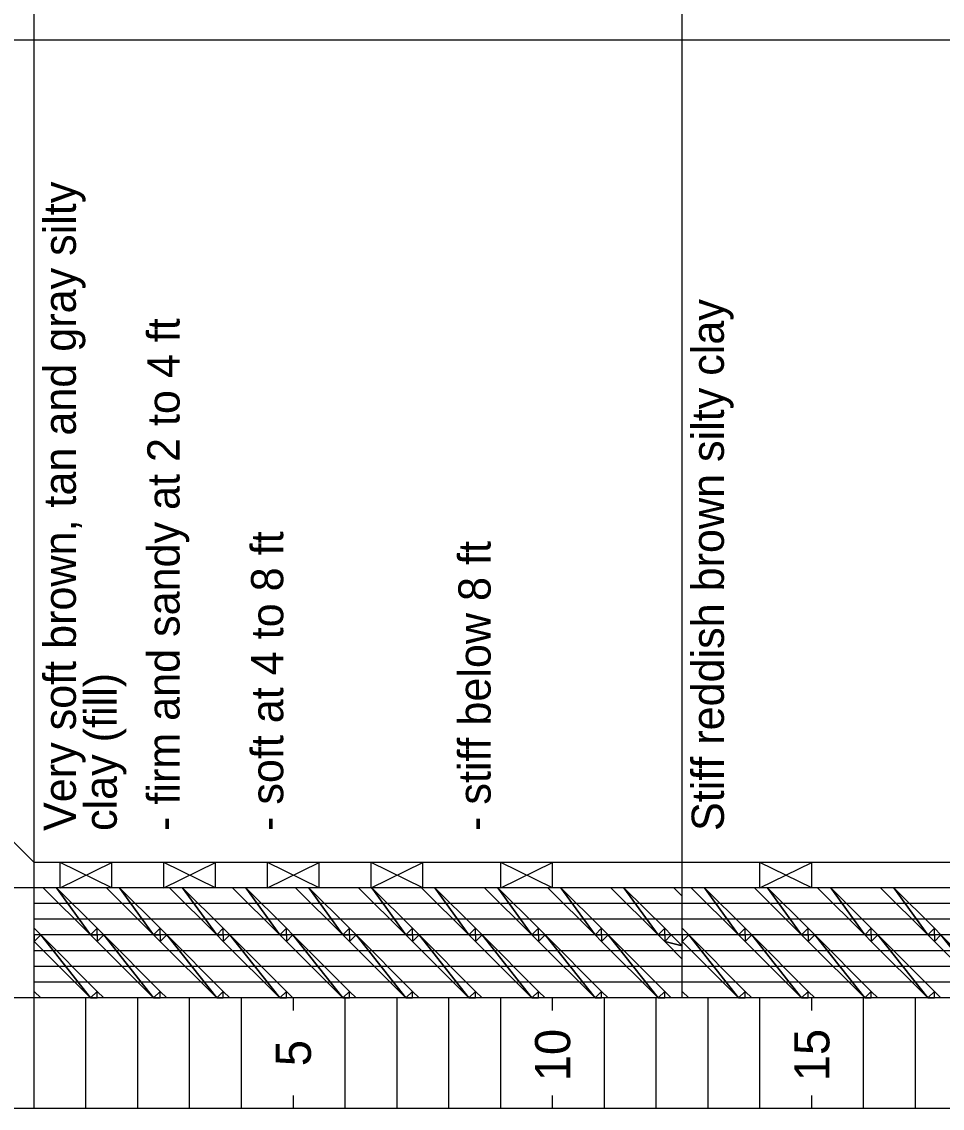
# Model space of a CAD drawing. Extents: x 1313964 to 1316843, y 2087046 to 2096619.
# Drawn here: x 1314089.05 to 1314106.81, y 2089818.7 to 2089839.67 of the extents above; entities that cross this region are included whole.
import ezdxf

# ---------------------------------------------------------------- set-up
doc = ezdxf.new("R2010")
doc.units = 0
doc.layers.add('B-Sub-Contour', color=7, linetype='Continuous')

msp = doc.modelspace()

# ---------------------------------------------------------------- linework, layer by layer
at = {"layer": 'B-Sub-Contour'}
for points in [[(1314136.725, 2089818.705), (1314136.725, 2089861.576), (1314075.306, 2089861.576), (1314075.306, 2089818.705), (1314136.725, 2089818.705)], [(1314089.292, 2089818.705), (1314089.292, 2089861.576)], [(1314101.792, 2089839.319), (1314101.792, 2089859.752)], [(1314134.292, 2089839.319), (1314082.603, 2089839.319)], [(1314101.792, 2089823.448), (1314101.792, 2089839.319)], [(1314089.292, 2089823.448), (1314088.745, 2089823.995)], [(1314134.292, 2089823.448), (1314089.292, 2089823.448)], [(1314089.792, 2089822.961), (1314090.792, 2089823.448)], [(1314090.792, 2089822.961), (1314089.792, 2089823.448)], [(1314089.792, 2089822.961), (1314089.792, 2089823.448)], [(1314090.792, 2089822.961), (1314090.792, 2089823.448)], [(1314091.792, 2089822.961), (1314092.792, 2089823.448)], [(1314092.792, 2089822.961), (1314091.792, 2089823.448)], [(1314091.792, 2089822.961), (1314091.792, 2089823.448)], [(1314092.792, 2089822.961), (1314092.792, 2089823.448)], [(1314093.792, 2089822.961), (1314094.792, 2089823.448)], [(1314094.792, 2089822.961), (1314093.792, 2089823.448)], [(1314093.792, 2089822.961), (1314093.792, 2089823.448)], [(1314094.792, 2089822.961), (1314094.792, 2089823.448)], [(1314095.792, 2089822.961), (1314096.792, 2089823.448)], [(1314096.792, 2089822.961), (1314095.792, 2089823.448)], [(1314095.792, 2089822.961), (1314095.792, 2089823.448)], [(1314096.792, 2089822.961), (1314096.792, 2089823.448)], [(1314098.292, 2089822.961), (1314099.292, 2089823.448)], [(1314099.292, 2089822.961), (1314098.292, 2089823.448)], [(1314098.292, 2089822.961), (1314098.292, 2089823.448)], [(1314099.292, 2089822.961), (1314099.292, 2089823.448)], [(1314101.792, 2089822.961), (1314101.792, 2089823.448)], [(1314103.292, 2089822.961), (1314104.292, 2089823.448)], [(1314104.292, 2089822.961), (1314103.292, 2089823.448)], [(1314103.292, 2089822.961), (1314103.292, 2089823.448)], [(1314104.292, 2089822.961), (1314104.292, 2089823.448)], [(1314134.292, 2089822.961), (1314082.603, 2089822.961)], [(1314101.792, 2089820.833), (1314101.792, 2089822.961)], [(1314101.792, 2089822.657), (1314089.292, 2089822.657)], [(1314117.292, 2089822.657), (1314101.792, 2089822.657)], [(1314101.792, 2089822.353), (1314089.292, 2089822.353)], [(1314117.292, 2089822.353), (1314101.792, 2089822.353)], [(1314101.792, 2089822.049), (1314089.292, 2089822.049)], [(1314117.292, 2089822.049), (1314101.792, 2089822.049)], [(1314101.792, 2089821.745), (1314089.292, 2089821.745)], [(1314117.292, 2089821.745), (1314101.792, 2089821.745)], [(1314101.792, 2089821.441), (1314089.292, 2089821.441)], [(1314117.292, 2089821.441), (1314101.792, 2089821.441)], [(1314101.792, 2089821.137), (1314089.292, 2089821.137)], [(1314117.292, 2089821.137), (1314101.792, 2089821.137)], [(1314134.292, 2089820.833), (1314082.603, 2089820.833)], [(1314089.292, 2089820.59), (1314089.292, 2089820.833)], [(1314089.292, 2089820.59), (1314089.292, 2089820.833)], [(1314090.292, 2089818.705), (1314090.292, 2089820.833)], [(1314091.292, 2089818.705), (1314091.292, 2089820.833)], [(1314091.292, 2089818.705), (1314091.292, 2089820.833)], [(1314092.292, 2089818.705), (1314092.292, 2089820.833)], [(1314093.292, 2089818.705), (1314093.292, 2089820.833)], [(1314093.292, 2089818.705), (1314093.292, 2089820.833)], [(1314094.292, 2089820.59), (1314094.292, 2089820.833)], [(1314095.292, 2089818.705), (1314095.292, 2089820.833)], [(1314095.292, 2089818.705), (1314095.292, 2089820.833)], [(1314096.292, 2089818.705), (1314096.292, 2089820.833)], [(1314097.292, 2089818.705), (1314097.292, 2089820.833)], [(1314097.292, 2089818.705), (1314097.292, 2089820.833)], [(1314098.292, 2089818.705), (1314098.292, 2089820.833)], [(1314099.292, 2089820.59), (1314099.292, 2089820.833)], [(1314099.292, 2089820.59), (1314099.292, 2089820.833)], [(1314100.292, 2089818.705), (1314100.292, 2089820.833)], [(1314101.292, 2089818.705), (1314101.292, 2089820.833)], [(1314101.292, 2089818.705), (1314101.292, 2089820.833)], [(1314102.292, 2089818.705), (1314102.292, 2089820.833)], [(1314103.292, 2089818.705), (1314103.292, 2089820.833)], [(1314103.292, 2089818.705), (1314103.292, 2089820.833)], [(1314104.292, 2089820.59), (1314104.292, 2089820.833)], [(1314105.292, 2089818.705), (1314105.292, 2089820.833)], [(1314105.292, 2089818.705), (1314105.292, 2089820.833)], [(1314106.292, 2089818.705), (1314106.292, 2089820.833)], [(1314089.292, 2089818.705), (1314089.292, 2089818.948)], [(1314089.292, 2089818.705), (1314089.292, 2089818.948)], [(1314094.292, 2089818.705), (1314094.292, 2089818.948)], [(1314099.292, 2089818.705), (1314099.292, 2089818.948)], [(1314099.292, 2089818.705), (1314099.292, 2089818.948)], [(1314104.292, 2089818.705), (1314104.292, 2089818.948)]]:
    msp.add_lwpolyline(points, dxfattribs=at)
for points in [[(1314090.381, 2089822.049), (1314089.724, 2089822.961), (1314089.468, 2089822.961), (1314090.381, 2089822.049)], [(1314090.381, 2089822.049), (1314090.509, 2089822.177), (1314089.724, 2089822.961), (1314090.381, 2089822.049)], [(1314091.597, 2089822.049), (1314090.94, 2089822.961), (1314090.685, 2089822.961), (1314091.597, 2089822.049)], [(1314091.597, 2089822.049), (1314091.725, 2089822.177), (1314090.94, 2089822.961), (1314091.597, 2089822.049)], [(1314092.813, 2089822.049), (1314092.157, 2089822.961), (1314091.901, 2089822.961), (1314092.813, 2089822.049)], [(1314092.813, 2089822.049), (1314092.941, 2089822.177), (1314092.157, 2089822.961), (1314092.813, 2089822.049)], [(1314094.03, 2089822.049), (1314093.373, 2089822.961), (1314093.117, 2089822.961), (1314094.03, 2089822.049)], [(1314094.03, 2089822.049), (1314094.157, 2089822.177), (1314093.373, 2089822.961), (1314094.03, 2089822.049)], [(1314095.246, 2089822.049), (1314094.589, 2089822.961), (1314094.334, 2089822.961), (1314095.246, 2089822.049)], [(1314095.246, 2089822.049), (1314095.374, 2089822.177), (1314094.589, 2089822.961), (1314095.246, 2089822.049)], [(1314096.462, 2089822.049), (1314095.805, 2089822.961), (1314095.55, 2089822.961), (1314096.462, 2089822.049)], [(1314096.462, 2089822.049), (1314096.59, 2089822.177), (1314095.805, 2089822.961), (1314096.462, 2089822.049)], [(1314097.678, 2089822.049), (1314097.021, 2089822.961), (1314096.766, 2089822.961), (1314097.678, 2089822.049)], [(1314097.678, 2089822.049), (1314097.806, 2089822.177), (1314097.021, 2089822.961), (1314097.678, 2089822.049)], [(1314098.894, 2089822.049), (1314098.238, 2089822.961), (1314097.982, 2089822.961), (1314098.894, 2089822.049)], [(1314098.894, 2089822.049), (1314099.022, 2089822.177), (1314098.238, 2089822.961), (1314098.894, 2089822.049)], [(1314100.111, 2089822.049), (1314099.454, 2089822.961), (1314099.199, 2089822.961), (1314100.111, 2089822.049)], [(1314100.111, 2089822.049), (1314100.238, 2089822.177), (1314099.454, 2089822.961), (1314100.111, 2089822.049)], [(1314101.327, 2089822.049), (1314100.67, 2089822.961), (1314100.415, 2089822.961), (1314101.327, 2089822.049)], [(1314101.327, 2089822.049), (1314101.455, 2089822.177), (1314100.67, 2089822.961), (1314101.327, 2089822.049)], [(1314101.792, 2089822.8), (1314101.792, 2089822.961), (1314101.631, 2089822.961), (1314101.792, 2089822.8)], [(1314102.881, 2089822.049), (1314102.224, 2089822.961), (1314101.968, 2089822.961), (1314102.881, 2089822.049)], [(1314102.881, 2089822.049), (1314103.009, 2089822.177), (1314102.224, 2089822.961), (1314102.881, 2089822.049)], [(1314104.097, 2089822.049), (1314103.44, 2089822.961), (1314103.185, 2089822.961), (1314104.097, 2089822.049)], [(1314104.097, 2089822.049), (1314104.225, 2089822.177), (1314103.44, 2089822.961), (1314104.097, 2089822.049)], [(1314105.313, 2089822.049), (1314104.657, 2089822.961), (1314104.401, 2089822.961), (1314105.313, 2089822.049)], [(1314105.313, 2089822.049), (1314105.441, 2089822.177), (1314104.657, 2089822.961), (1314105.313, 2089822.049)], [(1314106.53, 2089822.049), (1314105.873, 2089822.961), (1314105.617, 2089822.961), (1314106.53, 2089822.049)], [(1314106.53, 2089822.049), (1314106.657, 2089822.177), (1314105.873, 2089822.961), (1314106.53, 2089822.049)], [(1314089.42, 2089822.049), (1314089.292, 2089822.049), (1314089.292, 2089822.177), (1314089.42, 2089822.049)], [(1314089.42, 2089822.049), (1314089.292, 2089822.049), (1314089.292, 2089821.922), (1314089.42, 2089822.049)], [(1314090.381, 2089820.833), (1314089.42, 2089822.049), (1314089.292, 2089821.922), (1314090.381, 2089820.833)], [(1314090.381, 2089820.833), (1314090.509, 2089820.961), (1314089.42, 2089822.049), (1314090.381, 2089820.833)], [(1314090.381, 2089822.049), (1314090.509, 2089822.049), (1314090.509, 2089822.177), (1314090.381, 2089822.049)], [(1314090.509, 2089822.049), (1314090.509, 2089821.922), (1314090.381, 2089822.049), (1314090.509, 2089822.049)], [(1314090.636, 2089822.049), (1314090.509, 2089822.049), (1314090.509, 2089822.177), (1314090.636, 2089822.049)], [(1314090.636, 2089822.049), (1314090.509, 2089822.049), (1314090.509, 2089821.922), (1314090.636, 2089822.049)], [(1314091.597, 2089820.833), (1314090.636, 2089822.049), (1314090.509, 2089821.922), (1314091.597, 2089820.833)], [(1314091.597, 2089820.833), (1314091.725, 2089820.961), (1314090.636, 2089822.049), (1314091.597, 2089820.833)], [(1314091.597, 2089822.049), (1314091.725, 2089822.049), (1314091.725, 2089822.177), (1314091.597, 2089822.049)], [(1314091.725, 2089822.049), (1314091.725, 2089821.922), (1314091.597, 2089822.049), (1314091.725, 2089822.049)], [(1314091.853, 2089822.049), (1314091.725, 2089822.049), (1314091.725, 2089822.177), (1314091.853, 2089822.049)], [(1314091.853, 2089822.049), (1314091.725, 2089822.049), (1314091.725, 2089821.922), (1314091.853, 2089822.049)], [(1314092.813, 2089820.833), (1314091.853, 2089822.049), (1314091.725, 2089821.922), (1314092.813, 2089820.833)], [(1314092.813, 2089820.833), (1314092.941, 2089820.961), (1314091.853, 2089822.049), (1314092.813, 2089820.833)], [(1314092.813, 2089822.049), (1314092.941, 2089822.049), (1314092.941, 2089822.177), (1314092.813, 2089822.049)], [(1314092.941, 2089822.049), (1314092.941, 2089821.922), (1314092.813, 2089822.049), (1314092.941, 2089822.049)], [(1314093.069, 2089822.049), (1314092.941, 2089822.049), (1314092.941, 2089822.177), (1314093.069, 2089822.049)], [(1314093.069, 2089822.049), (1314092.941, 2089822.049), (1314092.941, 2089821.922), (1314093.069, 2089822.049)], [(1314094.03, 2089820.833), (1314093.069, 2089822.049), (1314092.941, 2089821.922), (1314094.03, 2089820.833)], [(1314094.03, 2089820.833), (1314094.157, 2089820.961), (1314093.069, 2089822.049), (1314094.03, 2089820.833)], [(1314094.03, 2089822.049), (1314094.157, 2089822.049), (1314094.157, 2089822.177), (1314094.03, 2089822.049)], [(1314094.157, 2089822.049), (1314094.157, 2089821.922), (1314094.03, 2089822.049), (1314094.157, 2089822.049)], [(1314094.285, 2089822.049), (1314094.157, 2089822.049), (1314094.157, 2089822.177), (1314094.285, 2089822.049)], [(1314094.285, 2089822.049), (1314094.157, 2089822.049), (1314094.157, 2089821.922), (1314094.285, 2089822.049)], [(1314095.246, 2089820.833), (1314094.285, 2089822.049), (1314094.157, 2089821.922), (1314095.246, 2089820.833)], [(1314095.246, 2089820.833), (1314095.374, 2089820.961), (1314094.285, 2089822.049), (1314095.246, 2089820.833)], [(1314095.246, 2089822.049), (1314095.374, 2089822.049), (1314095.374, 2089822.177), (1314095.246, 2089822.049)], [(1314095.374, 2089822.049), (1314095.374, 2089821.922), (1314095.246, 2089822.049), (1314095.374, 2089822.049)], [(1314095.501, 2089822.049), (1314095.374, 2089822.049), (1314095.374, 2089822.177), (1314095.501, 2089822.049)], [(1314095.501, 2089822.049), (1314095.374, 2089822.049), (1314095.374, 2089821.922), (1314095.501, 2089822.049)], [(1314096.462, 2089820.833), (1314095.501, 2089822.049), (1314095.374, 2089821.922), (1314096.462, 2089820.833)], [(1314096.462, 2089820.833), (1314096.59, 2089820.961), (1314095.501, 2089822.049), (1314096.462, 2089820.833)], [(1314096.462, 2089822.049), (1314096.59, 2089822.049), (1314096.59, 2089822.177), (1314096.462, 2089822.049)], [(1314096.59, 2089822.049), (1314096.59, 2089821.922), (1314096.462, 2089822.049), (1314096.59, 2089822.049)], [(1314096.717, 2089822.049), (1314096.59, 2089822.049), (1314096.59, 2089822.177), (1314096.717, 2089822.049)], [(1314096.717, 2089822.049), (1314096.59, 2089822.049), (1314096.59, 2089821.922), (1314096.717, 2089822.049)], [(1314097.678, 2089820.833), (1314096.717, 2089822.049), (1314096.59, 2089821.922), (1314097.678, 2089820.833)], [(1314097.678, 2089820.833), (1314097.806, 2089820.961), (1314096.717, 2089822.049), (1314097.678, 2089820.833)], [(1314097.678, 2089822.049), (1314097.806, 2089822.049), (1314097.806, 2089822.177), (1314097.678, 2089822.049)], [(1314097.806, 2089822.049), (1314097.806, 2089821.922), (1314097.678, 2089822.049), (1314097.806, 2089822.049)], [(1314097.934, 2089822.049), (1314097.806, 2089822.049), (1314097.806, 2089822.177), (1314097.934, 2089822.049)], [(1314097.934, 2089822.049), (1314097.806, 2089822.049), (1314097.806, 2089821.922), (1314097.934, 2089822.049)], [(1314098.894, 2089820.833), (1314097.934, 2089822.049), (1314097.806, 2089821.922), (1314098.894, 2089820.833)], [(1314098.894, 2089820.833), (1314099.022, 2089820.961), (1314097.934, 2089822.049), (1314098.894, 2089820.833)], [(1314098.894, 2089822.049), (1314099.022, 2089822.049), (1314099.022, 2089822.177), (1314098.894, 2089822.049)], [(1314099.022, 2089822.049), (1314099.022, 2089821.922), (1314098.894, 2089822.049), (1314099.022, 2089822.049)], [(1314099.15, 2089822.049), (1314099.022, 2089822.049), (1314099.022, 2089822.177), (1314099.15, 2089822.049)], [(1314099.15, 2089822.049), (1314099.022, 2089822.049), (1314099.022, 2089821.922), (1314099.15, 2089822.049)], [(1314100.111, 2089820.833), (1314099.15, 2089822.049), (1314099.022, 2089821.922), (1314100.111, 2089820.833)], [(1314100.111, 2089820.833), (1314100.238, 2089820.961), (1314099.15, 2089822.049), (1314100.111, 2089820.833)], [(1314100.111, 2089822.049), (1314100.238, 2089822.049), (1314100.238, 2089822.177), (1314100.111, 2089822.049)], [(1314100.238, 2089822.049), (1314100.238, 2089821.922), (1314100.111, 2089822.049), (1314100.238, 2089822.049)], [(1314100.366, 2089822.049), (1314100.238, 2089822.049), (1314100.238, 2089822.177), (1314100.366, 2089822.049)], [(1314100.366, 2089822.049), (1314100.238, 2089822.049), (1314100.238, 2089821.922), (1314100.366, 2089822.049)], [(1314101.327, 2089820.833), (1314100.366, 2089822.049), (1314100.238, 2089821.922), (1314101.327, 2089820.833)], [(1314101.327, 2089820.833), (1314101.455, 2089820.961), (1314100.366, 2089822.049), (1314101.327, 2089820.833)], [(1314101.327, 2089822.049), (1314101.455, 2089822.049), (1314101.455, 2089822.177), (1314101.327, 2089822.049)], [(1314101.455, 2089822.049), (1314101.455, 2089821.922), (1314101.327, 2089822.049), (1314101.455, 2089822.049)], [(1314101.582, 2089822.049), (1314101.455, 2089822.049), (1314101.455, 2089822.177), (1314101.582, 2089822.049)], [(1314101.582, 2089822.049), (1314101.455, 2089822.049), (1314101.455, 2089821.922), (1314101.582, 2089822.049)], [(1314101.455, 2089821.922), (1314101.792, 2089821.839), (1314101.582, 2089822.049), (1314101.455, 2089821.922)], [(1314101.92, 2089822.049), (1314101.792, 2089822.049), (1314101.792, 2089822.177), (1314101.92, 2089822.049)], [(1314101.92, 2089822.049), (1314101.792, 2089822.049), (1314101.792, 2089821.922), (1314101.92, 2089822.049)], [(1314102.881, 2089820.833), (1314101.92, 2089822.049), (1314101.792, 2089821.922), (1314102.881, 2089820.833)], [(1314102.881, 2089820.833), (1314103.009, 2089820.961), (1314101.92, 2089822.049), (1314102.881, 2089820.833)], [(1314102.881, 2089822.049), (1314103.009, 2089822.049), (1314103.009, 2089822.177), (1314102.881, 2089822.049)], [(1314103.009, 2089822.049), (1314103.009, 2089821.922), (1314102.881, 2089822.049), (1314103.009, 2089822.049)], [(1314103.136, 2089822.049), (1314103.009, 2089822.049), (1314103.009, 2089822.177), (1314103.136, 2089822.049)], [(1314103.136, 2089822.049), (1314103.009, 2089822.049), (1314103.009, 2089821.922), (1314103.136, 2089822.049)], [(1314104.097, 2089820.833), (1314103.136, 2089822.049), (1314103.009, 2089821.922), (1314104.097, 2089820.833)], [(1314104.097, 2089820.833), (1314104.225, 2089820.961), (1314103.136, 2089822.049), (1314104.097, 2089820.833)], [(1314104.097, 2089822.049), (1314104.225, 2089822.049), (1314104.225, 2089822.177), (1314104.097, 2089822.049)], [(1314104.225, 2089822.049), (1314104.225, 2089821.922), (1314104.097, 2089822.049), (1314104.225, 2089822.049)], [(1314104.353, 2089822.049), (1314104.225, 2089822.049), (1314104.225, 2089822.177), (1314104.353, 2089822.049)], [(1314104.353, 2089822.049), (1314104.225, 2089822.049), (1314104.225, 2089821.922), (1314104.353, 2089822.049)], [(1314105.313, 2089820.833), (1314104.353, 2089822.049), (1314104.225, 2089821.922), (1314105.313, 2089820.833)], [(1314105.313, 2089820.833), (1314105.441, 2089820.961), (1314104.353, 2089822.049), (1314105.313, 2089820.833)], [(1314105.313, 2089822.049), (1314105.441, 2089822.049), (1314105.441, 2089822.177), (1314105.313, 2089822.049)], [(1314105.441, 2089822.049), (1314105.441, 2089821.922), (1314105.313, 2089822.049), (1314105.441, 2089822.049)], [(1314105.569, 2089822.049), (1314105.441, 2089822.049), (1314105.441, 2089822.177), (1314105.569, 2089822.049)], [(1314105.569, 2089822.049), (1314105.441, 2089822.049), (1314105.441, 2089821.922), (1314105.569, 2089822.049)], [(1314106.53, 2089820.833), (1314105.569, 2089822.049), (1314105.441, 2089821.922), (1314106.53, 2089820.833)], [(1314106.53, 2089820.833), (1314106.657, 2089820.961), (1314105.569, 2089822.049), (1314106.53, 2089820.833)], [(1314106.53, 2089822.049), (1314106.657, 2089822.049), (1314106.657, 2089822.177), (1314106.53, 2089822.049)], [(1314106.657, 2089822.049), (1314106.657, 2089821.922), (1314106.53, 2089822.049), (1314106.657, 2089822.049)], [(1314106.785, 2089822.049), (1314106.657, 2089822.049), (1314106.657, 2089822.177), (1314106.785, 2089822.049)], [(1314106.785, 2089822.049), (1314106.657, 2089822.049), (1314106.657, 2089821.922), (1314106.785, 2089822.049)], [(1314107.746, 2089820.833), (1314106.785, 2089822.049), (1314106.657, 2089821.922), (1314107.746, 2089820.833)], [(1314107.746, 2089820.833), (1314107.874, 2089820.961), (1314106.785, 2089822.049), (1314107.746, 2089820.833)], [(1314101.455, 2089821.922), (1314101.792, 2089821.584), (1314101.792, 2089821.839), (1314101.455, 2089821.922)], [(1314089.42, 2089820.833), (1314089.292, 2089820.833), (1314089.292, 2089820.961), (1314089.42, 2089820.833)], [(1314090.381, 2089820.833), (1314090.509, 2089820.833), (1314090.509, 2089820.961), (1314090.381, 2089820.833)], [(1314090.636, 2089820.833), (1314090.509, 2089820.833), (1314090.509, 2089820.961), (1314090.636, 2089820.833)], [(1314091.597, 2089820.833), (1314091.725, 2089820.833), (1314091.725, 2089820.961), (1314091.597, 2089820.833)], [(1314091.853, 2089820.833), (1314091.725, 2089820.833), (1314091.725, 2089820.961), (1314091.853, 2089820.833)], [(1314092.813, 2089820.833), (1314092.941, 2089820.833), (1314092.941, 2089820.961), (1314092.813, 2089820.833)], [(1314093.069, 2089820.833), (1314092.941, 2089820.833), (1314092.941, 2089820.961), (1314093.069, 2089820.833)], [(1314094.03, 2089820.833), (1314094.157, 2089820.833), (1314094.157, 2089820.961), (1314094.03, 2089820.833)], [(1314094.285, 2089820.833), (1314094.157, 2089820.833), (1314094.157, 2089820.961), (1314094.285, 2089820.833)], [(1314095.246, 2089820.833), (1314095.374, 2089820.833), (1314095.374, 2089820.961), (1314095.246, 2089820.833)], [(1314095.501, 2089820.833), (1314095.374, 2089820.833), (1314095.374, 2089820.961), (1314095.501, 2089820.833)], [(1314096.462, 2089820.833), (1314096.59, 2089820.833), (1314096.59, 2089820.961), (1314096.462, 2089820.833)], [(1314096.717, 2089820.833), (1314096.59, 2089820.833), (1314096.59, 2089820.961), (1314096.717, 2089820.833)], [(1314097.678, 2089820.833), (1314097.806, 2089820.833), (1314097.806, 2089820.961), (1314097.678, 2089820.833)], [(1314097.934, 2089820.833), (1314097.806, 2089820.833), (1314097.806, 2089820.961), (1314097.934, 2089820.833)], [(1314098.894, 2089820.833), (1314099.022, 2089820.833), (1314099.022, 2089820.961), (1314098.894, 2089820.833)], [(1314099.15, 2089820.833), (1314099.022, 2089820.833), (1314099.022, 2089820.961), (1314099.15, 2089820.833)], [(1314100.111, 2089820.833), (1314100.238, 2089820.833), (1314100.238, 2089820.961), (1314100.111, 2089820.833)], [(1314100.366, 2089820.833), (1314100.238, 2089820.833), (1314100.238, 2089820.961), (1314100.366, 2089820.833)], [(1314101.327, 2089820.833), (1314101.455, 2089820.833), (1314101.455, 2089820.961), (1314101.327, 2089820.833)], [(1314101.582, 2089820.833), (1314101.455, 2089820.833), (1314101.455, 2089820.961), (1314101.582, 2089820.833)], [(1314101.92, 2089820.833), (1314101.792, 2089820.833), (1314101.792, 2089820.961), (1314101.92, 2089820.833)], [(1314102.881, 2089820.833), (1314103.009, 2089820.833), (1314103.009, 2089820.961), (1314102.881, 2089820.833)], [(1314103.136, 2089820.833), (1314103.009, 2089820.833), (1314103.009, 2089820.961), (1314103.136, 2089820.833)], [(1314104.097, 2089820.833), (1314104.225, 2089820.833), (1314104.225, 2089820.961), (1314104.097, 2089820.833)], [(1314104.353, 2089820.833), (1314104.225, 2089820.833), (1314104.225, 2089820.961), (1314104.353, 2089820.833)], [(1314105.313, 2089820.833), (1314105.441, 2089820.833), (1314105.441, 2089820.961), (1314105.313, 2089820.833)], [(1314105.569, 2089820.833), (1314105.441, 2089820.833), (1314105.441, 2089820.961), (1314105.569, 2089820.833)], [(1314106.53, 2089820.833), (1314106.657, 2089820.833), (1314106.657, 2089820.961), (1314106.53, 2089820.833)], [(1314106.785, 2089820.833), (1314106.657, 2089820.833), (1314106.657, 2089820.961), (1314106.785, 2089820.833)]]:
    msp.add_lwpolyline(points, close=True, dxfattribs=at)

# ---------------------------------------------------------------- texts
for s, height, p in [('Very soft brown, tan and gray silty', 0.62209, (1314090.097, 2089824.056)), ('Stiff reddish brown silty clay', 0.62209, (1314102.597, 2089824.056)), ('- firm and sandy at 2 to 4 ft', 0.62209, (1314092.097, 2089824.056)), ('- soft at 4 to 8 ft', 0.62209, (1314094.097, 2089824.056)), ('- stiff below 8 ft', 0.62209, (1314098.097, 2089824.056)), ('clay (fill)', 0.62209, (1314090.886, 2089824.056)), ('10', 0.6786, (1314099.632, 2089819.227)), ('10', 0.6786, (1314099.632, 2089819.227)), ('15', 0.6786, (1314104.632, 2089819.227)), ('5', 0.679, (1314094.632, 2089819.517))]:
    msp.add_text(s, height=height, rotation=90, dxfattribs=at).set_placement(p)

doc.saveas('drawing.dxf')
